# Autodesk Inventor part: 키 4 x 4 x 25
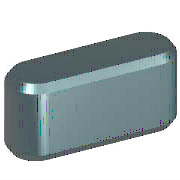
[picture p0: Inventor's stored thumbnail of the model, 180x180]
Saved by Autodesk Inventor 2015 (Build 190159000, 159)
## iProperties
IsCustomPart: 1
Created: 2012-02
Part Number: 키 4 x 4 x 25
Material: 강철, 연강
Description: 키 및 해당 키홈
Document SubType Name: Modeling
Standard: KS B 1311
Designer: mduedu
Standards Organization: KS
Language: ko-KR
Size Designation: 4 x 4 x 25
Categories: <MemberInstance><Categories><Category DisplayName="샤프트 부품" InternalName="7f7aeb1f-a693-4053-b835-cee3144e0d98" Mnemonic="SHFT"><Category DisplayName="키" Interna
Density: 1 g/cm^3
Appearance: 노란색
Author: mduedu
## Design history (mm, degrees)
workplane "Work Plane1"
workplane "Work Plane2"
sketch "스케치1"
  geometry: L1 (2, 2)-(23, 2); L2 (23, -2)-(2, -2); L3 (0, 9.4)-(0, -7.4) reference; L4 (-5, 0)-(30, 0) reference; L5 (25, 0)-(25, 7); A1 r 2 centre (2, 0) between (2, 2) and (2, -2); A2 r 2 centre (23, 0) between (23, -2) and (23, 2)
  constraints: 6 end point, 5 point on circle, 4 tangent, 3 point on line, 2 centre point, 1 horizontal, 1 parallel, 1 perpendicular
  dimensions: "d0" = 2 radius of A1 (= 0.5 x PB); "d13" = 2 radius of A2 (= 0.5 x PB); "d14" = 25 distance between parallel lines of L5 L3 (= NLG)
extrude "본체1" new body sketch "스케치1" taper "d3" = 0 deg; stored distance "d4" = 10
workplane "Work Plane3"
body "Solid1"
chamfer "모따기1" distance "d8" = 0.25 (= PHH); stored, may be unused: second distance "d9" = 0.25 (= PHH), angle "d15" = 45 deg
other parameters: "d1" = -2.5 (= -PNT), "d2" = 1.5 (= PH - PNT), "NLG" = 25 [user parameter; used in 3 equation terms], "PB" = 4 [user parameter; used in 2 equation terms], "PNT" = 2.5 [user parameter; used in 2 equation terms], "PH" = 4 [user parameter; used in 1 equation term], "PHH" = 0.25 [user parameter; used in 2 equation terms], "d10" = 0, "d16" = 0, "d17" = 0, "d18" = 0, "PLB2" = 25 (= NLG) [user parameter], "WDMAX" = 12 [user parameter], "PLB1" = 25 (= NLG) [user parameter], "RR" = 0.08 [user parameter], "PUEB" = 1.8 [user parameter]
